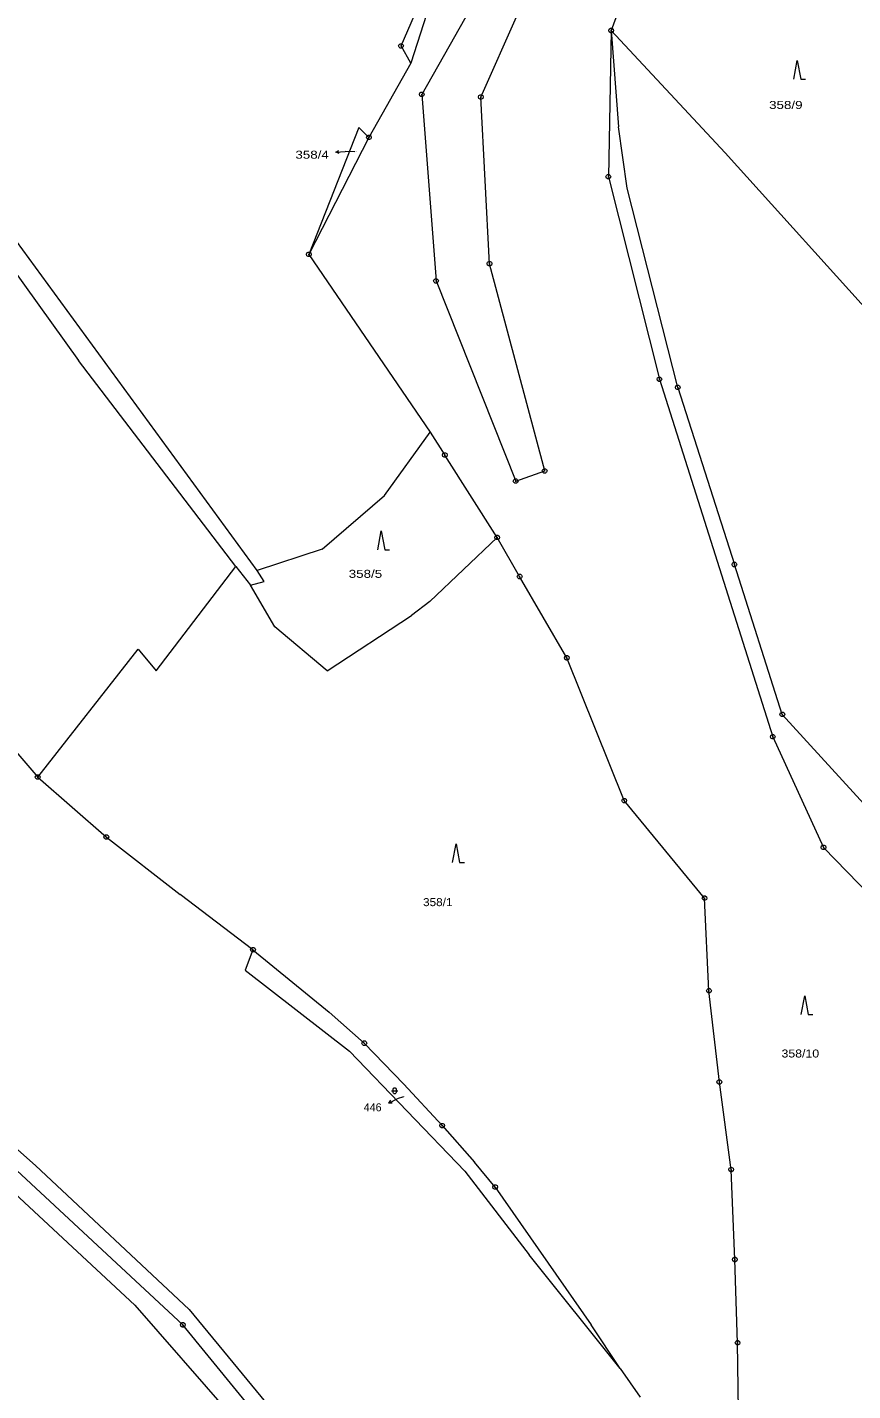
# Model space of a CAD drawing. Extents: x -687390 to -684106, y -954833 to -951648.
# Drawn here: x -686369.8 to -686194.5, y -953282.2 to -952992.5 of the extents above; entities that cross this region are included whole.
import ezdxf
from ezdxf.enums import TextEntityAlignment as Align

# ---------------------------------------------------------------- set-up
doc = ezdxf.new("R2010")
doc.units = 0
doc.header["$LTSCALE"] = 0.68
for name, color, linetype, lineweight in [('1', 7, 'Continuous', 13), ('3', 7, 'Continuous', 13), ('7', 7, 'Continuous', 13), ('8', 7, 'Continuous', 13)]:
    doc.layers.add(name, color=color, linetype=linetype, lineweight=lineweight)
doc.layers.add('2', color=7, linetype='Continuous')

msp = doc.modelspace()

# ---------------------------------------------------------------- linework, layer by layer
at = {"layer": '1'}
for p, q in [((-686290.41, -952996.5), (-686283.96, -952981.54)), ((-686245.78, -952993.22), (-686244.19, -953013.66)), ((-686245.78, -952993.22), (-686221.57, -953019.23)), ((-686288.36, -953000.15), (-686290.41, -952996.5)), ((-686221.57, -953019.23), (-686166.55, -953080.22)), ((-686320.99, -953107.93), (-686379.12, -953028.38)), ((-686381.78, -953031.54), (-686358.91, -953063.3)), ((-686325.48, -953107.07), (-686358.91, -953063.3)), ((-686231.62, -953069.04), (-686219.59, -953106.68)), ((-686284.2, -953078.53), (-686281.1, -953083.41)), ((-686269.97, -953100.92), (-686281.1, -953083.41)), ((-686307.16, -953103.39), (-686320.99, -953107.93)), ((-686269.97, -953100.92), (-686284.3, -953114.5)), ((-686209.41, -953138.51), (-686219.59, -953106.68)), ((-686284.3, -953114.5), (-686288.21, -953117.51)), ((-686306.09, -953129.29), (-686288.21, -953117.51)), ((-686353.01, -953164.57), (-686337.36, -953176.8)), ((-686321.86, -953188.51), (-686337.36, -953176.8)), ((-686321.86, -953188.51), (-686305.7, -953201.78)), ((-686298.21, -953208.37), (-686305.7, -953201.78)), ((-686298.21, -953208.37), (-686289.81, -953217.04)), ((-686281.67, -953225.88), (-686289.81, -953217.04)), ((-686281.67, -953225.88), (-686274.77, -953233.68)), ((-686270.41, -953238.93), (-686274.77, -953233.68)), ((-686276.84, -953235.55), (-686263.19, -953253.3)), ((-686270.41, -953238.93), (-686250.03, -953268.24)), ((-686243.83, -953277.51), (-686263.19, -953253.3)), ((-686243.83, -953277.51), (-686250.03, -953268.24)), ((-686243.83, -953277.51), (-686239.59, -953283.6))]:
    msp.add_line(p, q, dxfattribs=at)
for points in [[(-686277.63, -952966.87), (-686264.71, -952957.38), (-686265.17, -952970.01), (-686286.01, -953006.79), (-686282.98, -953046.43), (-686266.05, -953088.96), (-686259.89, -953086.79), (-686271.62, -953042.76), (-686273.46, -953007.35), (-686257.73, -952971.92), (-686249.15, -952961.96), (-686236.01, -952966.66), (-686245.78, -952993.22), (-686246.36, -953024.29), (-686235.52, -953067.32), (-686211.44, -953143.28)], [(-686498.08, -952961.98), (-686495.25, -952967.14), (-686459.74, -953032.55), (-686443.92, -953056.89), (-686425.27, -953082.18), (-686401.26, -953112.58), (-686367.6, -953151.83), (-686353.01, -953164.57)], [(-686277.63, -952966.87), (-686288.36, -953000.15), (-686297.23, -953015.92), (-686310, -953040.78), (-686284.2, -953078.53)], [(-686297.23, -953015.92), (-686299.34, -953013.79), (-686310, -953040.78)], [(-686231.62, -953069.04), (-686242.4, -953026.71), (-686244.19, -953013.66)], [(-686252.58, -953389.33), (-686292.75, -953324.92), (-686302.57, -953310.07), (-686336.76, -953268.21), (-686375.07, -953232.58), (-686400.17, -953211.88), (-686416.48, -953192.52), (-686437.08, -953164.4), (-686477, -953119.5), (-686503.23, -953091.93), (-686517.39, -953073.32), (-686528.9, -953057.45), (-686535.29, -953045.19), (-686542.46, -953027.04)], [(-686307.16, -953103.39), (-686293.95, -953092), (-686284.2, -953078.53)], [(-686217.88, -953325.3), (-686218.48, -953300.81), (-686218.91, -953272.03), (-686219.51, -953254.33), (-686220.28, -953235.24), (-686222.79, -953216.62), (-686224.99, -953197.24), (-686225.92, -953177.55), (-686242.98, -953156.84), (-686255.19, -953126.51), (-686265.21, -953109.22), (-686269.97, -953100.92)], [(-686367.6, -953151.83), (-686346.26, -953124.64), (-686342.4, -953129.26), (-686325.48, -953107.07), (-686322.38, -953111.03)], [(-686306.09, -953129.29), (-686317.25, -953119.94), (-686322.38, -953111.03), (-686319.48, -953110.26), (-686320.99, -953107.93)], [(-686108.06, -953262.93), (-686109.21, -953248.25), (-686209.41, -953138.51)], [(-686211.44, -953143.28), (-686200.65, -953166.77), (-686173.14, -953195.14), (-686183.3, -953209.46), (-686177.18, -953239.95), (-686180.55, -953270.73), (-686185.51, -953316.35), (-686174.31, -953368.93)], [(-686321.86, -953188.51), (-686323.49, -953192.85), (-686301.37, -953210.08), (-686276.84, -953235.55)], [(-686378.72, -953224.93), (-686368.07, -953234.36), (-686335.41, -953264.98), (-686302.65, -953304.78), (-686292.4, -953318.9)], [(-686379.66, -953233.62), (-686346.95, -953264.02), (-686326.9, -953287)]]:
    msp.add_lwpolyline(points, dxfattribs=at)
at = {"layer": '3'}
for points in [[(-686206.99, -953003.56), (-686206.24, -952999.56), (-686205.49, -953003.56), (-686204.49, -953003.56)], [(-686295.35, -953103.52), (-686294.6, -953099.52), (-686293.85, -953103.52), (-686292.85, -953103.52)], [(-686279.46, -953169.98), (-686278.71, -953165.98), (-686277.96, -953169.98), (-686276.96, -953169.98)], [(-686205.4, -953202.28), (-686204.65, -953198.28), (-686203.9, -953202.28), (-686202.9, -953202.28)], [(-686292.44, -953218.48), (-686291.589, -953218.48), (-686291.1, -953218.48)]]:
    msp.add_lwpolyline(points, dxfattribs=at)
msp.add_lwpolyline([(-686292.105, -953218.145), (-686292.038, -953217.951), (-686291.87, -953217.83), (-686291.663, -953217.83), (-686291.495, -953217.951), (-686291.428, -953218.145), (-686291.428, -953218.815), (-686291.495, -953219.009), (-686291.663, -953219.13), (-686291.87, -953219.13), (-686292.038, -953219.009), (-686292.105, -953218.815)], close=True, dxfattribs=at)
at = {"layer": '7'}
for p, q in [((-686304.271, -953019.085), (-686302.27, -953018.89)), ((-686300.22, -953018.98), (-686302.27, -953018.89)), ((-686293.023, -953221.099), (-686291.22, -953220.21)), ((-686289.89, -953219.77), (-686291.22, -953220.21))]:
    msp.add_line(p, q, dxfattribs=at)
for points in [[(-686303.571, -953019.353), (-686304.271, -953019.085), (-686303.636, -953018.687)], [(-686292.274, -953221.103), (-686293.023, -953221.099), (-686292.57, -953220.502)]]:
    msp.add_lwpolyline(points, dxfattribs=at)
at = {"layer": '8'}
for p, q in [((-686245.9, -952993.22), (-686245.66, -952993.22)), ((-686290.53, -952996.5), (-686290.29, -952996.5)), ((-686286.13, -953006.79), (-686285.89, -953006.79)), ((-686273.58, -953007.35), (-686273.34, -953007.35)), ((-686297.35, -953015.92), (-686297.11, -953015.92)), ((-686246.48, -953024.29), (-686246.24, -953024.29)), ((-686310.12, -953040.78), (-686309.88, -953040.78)), ((-686271.74, -953042.76), (-686271.5, -953042.76)), ((-686283.1, -953046.43), (-686282.86, -953046.43)), ((-686235.64, -953067.32), (-686235.4, -953067.32)), ((-686231.74, -953069.04), (-686231.5, -953069.04)), ((-686281.22, -953083.41), (-686280.98, -953083.41)), ((-686266.17, -953088.96), (-686265.93, -953088.96)), ((-686260.01, -953086.79), (-686259.77, -953086.79)), ((-686270.09, -953100.92), (-686269.85, -953100.92)), ((-686219.71, -953106.68), (-686219.47, -953106.68)), ((-686265.33, -953109.22), (-686265.09, -953109.22)), ((-686255.31, -953126.51), (-686255.07, -953126.51)), ((-686209.53, -953138.51), (-686209.29, -953138.51)), ((-686211.56, -953143.28), (-686211.32, -953143.28)), ((-686367.72, -953151.83), (-686367.48, -953151.83)), ((-686243.1, -953156.84), (-686242.86, -953156.84)), ((-686353.13, -953164.57), (-686352.89, -953164.57)), ((-686200.77, -953166.77), (-686200.53, -953166.77)), ((-686226.04, -953177.55), (-686225.8, -953177.55)), ((-686321.98, -953188.51), (-686321.74, -953188.51)), ((-686225.11, -953197.24), (-686224.87, -953197.24)), ((-686298.33, -953208.37), (-686298.09, -953208.37)), ((-686222.91, -953216.62), (-686222.67, -953216.62)), ((-686281.79, -953225.88), (-686281.55, -953225.88)), ((-686220.4, -953235.24), (-686220.16, -953235.24)), ((-686270.53, -953238.93), (-686270.29, -953238.93)), ((-686219.63, -953254.33), (-686219.39, -953254.33)), ((-686336.88, -953268.21), (-686336.64, -953268.21)), ((-686219.03, -953272.03), (-686218.79, -953272.03))]:
    msp.add_line(p, q, dxfattribs=at)
for points in [[(-686245.63, -952992.74), (-686245.38, -952992.92), (-686245.28, -952993.21), (-686245.38, -952993.5), (-686245.63, -952993.68), (-686245.94, -952993.68), (-686246.19, -952993.5), (-686246.29, -952993.21), (-686246.19, -952992.92), (-686245.94, -952992.74)], [(-686290.26, -952996.02), (-686290.01, -952996.2), (-686289.91, -952996.49), (-686290.01, -952996.78), (-686290.26, -952996.96), (-686290.57, -952996.96), (-686290.82, -952996.78), (-686290.92, -952996.49), (-686290.82, -952996.2), (-686290.57, -952996.02)], [(-686285.86, -953006.31), (-686285.61, -953006.49), (-686285.51, -953006.78), (-686285.61, -953007.07), (-686285.86, -953007.25), (-686286.17, -953007.25), (-686286.42, -953007.07), (-686286.52, -953006.78), (-686286.42, -953006.49), (-686286.17, -953006.31)], [(-686273.31, -953006.87), (-686273.06, -953007.05), (-686272.96, -953007.34), (-686273.06, -953007.63), (-686273.31, -953007.81), (-686273.62, -953007.81), (-686273.87, -953007.63), (-686273.97, -953007.34), (-686273.87, -953007.05), (-686273.62, -953006.87)], [(-686297.08, -953015.44), (-686296.83, -953015.62), (-686296.73, -953015.91), (-686296.83, -953016.2), (-686297.08, -953016.38), (-686297.39, -953016.38), (-686297.64, -953016.2), (-686297.74, -953015.91), (-686297.64, -953015.62), (-686297.39, -953015.44)], [(-686246.21, -953023.81), (-686245.96, -953023.99), (-686245.86, -953024.28), (-686245.96, -953024.57), (-686246.21, -953024.75), (-686246.52, -953024.75), (-686246.77, -953024.57), (-686246.87, -953024.28), (-686246.77, -953023.99), (-686246.52, -953023.81)], [(-686309.85, -953040.3), (-686309.6, -953040.48), (-686309.5, -953040.77), (-686309.6, -953041.06), (-686309.85, -953041.24), (-686310.16, -953041.24), (-686310.41, -953041.06), (-686310.51, -953040.77), (-686310.41, -953040.48), (-686310.16, -953040.3)], [(-686271.47, -953042.28), (-686271.22, -953042.46), (-686271.12, -953042.75), (-686271.22, -953043.04), (-686271.47, -953043.22), (-686271.78, -953043.22), (-686272.03, -953043.04), (-686272.13, -953042.75), (-686272.03, -953042.46), (-686271.78, -953042.28)], [(-686282.83, -953045.95), (-686282.58, -953046.13), (-686282.48, -953046.42), (-686282.58, -953046.71), (-686282.83, -953046.89), (-686283.14, -953046.89), (-686283.39, -953046.71), (-686283.49, -953046.42), (-686283.39, -953046.13), (-686283.14, -953045.95)], [(-686235.37, -953066.84), (-686235.12, -953067.02), (-686235.02, -953067.31), (-686235.12, -953067.6), (-686235.37, -953067.78), (-686235.68, -953067.78), (-686235.93, -953067.6), (-686236.03, -953067.31), (-686235.93, -953067.02), (-686235.68, -953066.84)], [(-686231.47, -953068.56), (-686231.22, -953068.74), (-686231.12, -953069.03), (-686231.22, -953069.32), (-686231.47, -953069.5), (-686231.78, -953069.5), (-686232.03, -953069.32), (-686232.13, -953069.03), (-686232.03, -953068.74), (-686231.78, -953068.56)], [(-686280.95, -953082.93), (-686280.7, -953083.11), (-686280.6, -953083.4), (-686280.7, -953083.69), (-686280.95, -953083.87), (-686281.26, -953083.87), (-686281.51, -953083.69), (-686281.61, -953083.4), (-686281.51, -953083.11), (-686281.26, -953082.93)], [(-686259.74, -953086.31), (-686259.49, -953086.49), (-686259.39, -953086.78), (-686259.49, -953087.07), (-686259.74, -953087.25), (-686260.05, -953087.25), (-686260.3, -953087.07), (-686260.4, -953086.78), (-686260.3, -953086.49), (-686260.05, -953086.31)], [(-686265.9, -953088.48), (-686265.65, -953088.66), (-686265.55, -953088.95), (-686265.65, -953089.24), (-686265.9, -953089.42), (-686266.21, -953089.42), (-686266.46, -953089.24), (-686266.56, -953088.95), (-686266.46, -953088.66), (-686266.21, -953088.48)], [(-686269.82, -953100.44), (-686269.57, -953100.62), (-686269.47, -953100.91), (-686269.57, -953101.2), (-686269.82, -953101.38), (-686270.13, -953101.38), (-686270.38, -953101.2), (-686270.48, -953100.91), (-686270.38, -953100.62), (-686270.13, -953100.44)], [(-686219.44, -953106.2), (-686219.19, -953106.38), (-686219.09, -953106.67), (-686219.19, -953106.96), (-686219.44, -953107.14), (-686219.75, -953107.14), (-686220, -953106.96), (-686220.1, -953106.67), (-686220, -953106.38), (-686219.75, -953106.2)], [(-686265.06, -953108.74), (-686264.81, -953108.92), (-686264.71, -953109.21), (-686264.81, -953109.5), (-686265.06, -953109.68), (-686265.37, -953109.68), (-686265.62, -953109.5), (-686265.72, -953109.21), (-686265.62, -953108.92), (-686265.37, -953108.74)], [(-686255.04, -953126.03), (-686254.79, -953126.21), (-686254.69, -953126.5), (-686254.79, -953126.79), (-686255.04, -953126.97), (-686255.35, -953126.97), (-686255.6, -953126.79), (-686255.7, -953126.5), (-686255.6, -953126.21), (-686255.35, -953126.03)], [(-686209.26, -953138.03), (-686209.01, -953138.21), (-686208.91, -953138.5), (-686209.01, -953138.79), (-686209.26, -953138.97), (-686209.57, -953138.97), (-686209.82, -953138.79), (-686209.92, -953138.5), (-686209.82, -953138.21), (-686209.57, -953138.03)], [(-686211.29, -953142.8), (-686211.04, -953142.98), (-686210.94, -953143.27), (-686211.04, -953143.56), (-686211.29, -953143.74), (-686211.6, -953143.74), (-686211.85, -953143.56), (-686211.95, -953143.27), (-686211.85, -953142.98), (-686211.6, -953142.8)], [(-686367.45, -953151.35), (-686367.2, -953151.53), (-686367.1, -953151.82), (-686367.2, -953152.11), (-686367.45, -953152.29), (-686367.76, -953152.29), (-686368.01, -953152.11), (-686368.11, -953151.82), (-686368.01, -953151.53), (-686367.76, -953151.35)], [(-686242.83, -953156.36), (-686242.58, -953156.54), (-686242.48, -953156.83), (-686242.58, -953157.12), (-686242.83, -953157.3), (-686243.14, -953157.3), (-686243.39, -953157.12), (-686243.49, -953156.83), (-686243.39, -953156.54), (-686243.14, -953156.36)], [(-686352.86, -953164.09), (-686352.61, -953164.27), (-686352.51, -953164.56), (-686352.61, -953164.85), (-686352.86, -953165.03), (-686353.17, -953165.03), (-686353.42, -953164.85), (-686353.52, -953164.56), (-686353.42, -953164.27), (-686353.17, -953164.09)], [(-686200.5, -953166.29), (-686200.25, -953166.47), (-686200.15, -953166.76), (-686200.25, -953167.05), (-686200.5, -953167.23), (-686200.81, -953167.23), (-686201.06, -953167.05), (-686201.16, -953166.76), (-686201.06, -953166.47), (-686200.81, -953166.29)], [(-686225.77, -953177.07), (-686225.52, -953177.25), (-686225.42, -953177.54), (-686225.52, -953177.83), (-686225.77, -953178.01), (-686226.08, -953178.01), (-686226.33, -953177.83), (-686226.43, -953177.54), (-686226.33, -953177.25), (-686226.08, -953177.07)], [(-686321.71, -953188.03), (-686321.46, -953188.21), (-686321.36, -953188.5), (-686321.46, -953188.79), (-686321.71, -953188.97), (-686322.02, -953188.97), (-686322.27, -953188.79), (-686322.37, -953188.5), (-686322.27, -953188.21), (-686322.02, -953188.03)], [(-686224.84, -953196.76), (-686224.59, -953196.94), (-686224.49, -953197.23), (-686224.59, -953197.52), (-686224.84, -953197.7), (-686225.15, -953197.7), (-686225.4, -953197.52), (-686225.5, -953197.23), (-686225.4, -953196.94), (-686225.15, -953196.76)], [(-686298.06, -953207.89), (-686297.81, -953208.07), (-686297.71, -953208.36), (-686297.81, -953208.65), (-686298.06, -953208.83), (-686298.37, -953208.83), (-686298.62, -953208.65), (-686298.72, -953208.36), (-686298.62, -953208.07), (-686298.37, -953207.89)], [(-686222.64, -953216.14), (-686222.39, -953216.32), (-686222.29, -953216.61), (-686222.39, -953216.9), (-686222.64, -953217.08), (-686222.95, -953217.08), (-686223.2, -953216.9), (-686223.3, -953216.61), (-686223.2, -953216.32), (-686222.95, -953216.14)], [(-686281.52, -953225.4), (-686281.27, -953225.58), (-686281.17, -953225.87), (-686281.27, -953226.16), (-686281.52, -953226.34), (-686281.83, -953226.34), (-686282.08, -953226.16), (-686282.18, -953225.87), (-686282.08, -953225.58), (-686281.83, -953225.4)], [(-686220.13, -953234.76), (-686219.88, -953234.94), (-686219.78, -953235.23), (-686219.88, -953235.52), (-686220.13, -953235.7), (-686220.44, -953235.7), (-686220.69, -953235.52), (-686220.79, -953235.23), (-686220.69, -953234.94), (-686220.44, -953234.76)], [(-686270.26, -953238.45), (-686270.01, -953238.63), (-686269.91, -953238.92), (-686270.01, -953239.21), (-686270.26, -953239.39), (-686270.57, -953239.39), (-686270.82, -953239.21), (-686270.92, -953238.92), (-686270.82, -953238.63), (-686270.57, -953238.45)], [(-686219.36, -953253.85), (-686219.11, -953254.03), (-686219.01, -953254.32), (-686219.11, -953254.61), (-686219.36, -953254.79), (-686219.67, -953254.79), (-686219.92, -953254.61), (-686220.02, -953254.32), (-686219.92, -953254.03), (-686219.67, -953253.85)], [(-686336.61, -953267.73), (-686336.36, -953267.91), (-686336.26, -953268.2), (-686336.36, -953268.49), (-686336.61, -953268.67), (-686336.92, -953268.67), (-686337.17, -953268.49), (-686337.27, -953268.2), (-686337.17, -953267.91), (-686336.92, -953267.73)], [(-686218.76, -953271.55), (-686218.51, -953271.73), (-686218.41, -953272.02), (-686218.51, -953272.31), (-686218.76, -953272.49), (-686219.07, -953272.49), (-686219.32, -953272.31), (-686219.42, -953272.02), (-686219.32, -953271.73), (-686219.07, -953271.55)]]:
    msp.add_lwpolyline(points, close=True, dxfattribs=at)

# ---------------------------------------------------------------- texts
at = {"layer": '2'}
for s, height, width, p in [('358/9', 1.7, 1.25, (-686212.225, -953009.88)), ('358/4', 0.1, 1.25, (-686300.192, -953018.98)), ('358/5', 1.7, 1.25, (-686301.525, -953109.5)), ('358/1', 1.7, 1.1, (-686285.735, -953179.25)), ('358/10', 1.7, 1.15, (-686209.585, -953211.41))]:
    msp.add_text(s, height=height, dxfattribs=dict(at, width=width)).set_placement(p)
msp.add_text('446', height=0.1, dxfattribs=at).set_placement((-686289.862, -953219.77))
at = {"layer": '7', "width": 1.25}
msp.add_text('358/4', height=1.7, dxfattribs=at).set_placement((-686305.746, -953020.45), align=Align.RIGHT)
at = {"layer": '7'}
msp.add_text('446', height=1.7, dxfattribs=at).set_placement((-686294.546, -953222.84), align=Align.RIGHT)

doc.saveas('drawing.dxf')
